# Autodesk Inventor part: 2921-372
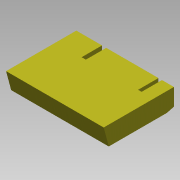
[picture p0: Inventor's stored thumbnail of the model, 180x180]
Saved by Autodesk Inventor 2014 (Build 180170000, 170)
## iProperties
Company: NHTSA/VRTC
Created: 2012-02
Part Number: 2921-372
Project: CHILD SIDE IMPACT SLED
Material: Polyurethane Foam
Description: SEAT BOTTOM CUSHION
Document SubType Name: Modeling
Designer: Dave Walker
Mass: 26828.4 g
Surface Area: 10956.6 cm^2
Volume: 42721.2 cm^3
Density: 0.627988 g/cm^3
Appearance: Canary
Title: Seat Bottom Cushion
Subject: Child Side Impact Sled
Author: Dave Walker
Comments: POLYURETHANE FOAM DENSITY ACCORDING TO ISO 485 (kg/m³)  BEARING STRENGTH ACCORDING TO ISO 2439B (N) p - 25% p - 40% BEARING STRENGTH FACTOR ACCORDEING TO ISO 3386 (kPa) ELONGATION AT RUPTURE ACCORDING
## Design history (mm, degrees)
sketch "Sketch2"
  geometry: L1 (-450, 135)-(50, 135); L2 (50, 135)-(50, 13.397); L3 (0, 0)-(-413.827, 0); L4 (-413.827, 0)-(-450, 135); L5 (0, 0)-(50, 13.397); 1 further point
  constraints: 10 end point, 1 coincident, 1 horizontal, 1 parallel, 1 vertical
  dimensions: "d9" = 15 deg angle of L3 L5; "d32" = 135 distance between parallel lines of L1 L3; "d34" = 500 horizontal distance of L2.end L1.start; "d35" = 50 horizontal distance of L2.end L3.start; "d37" = 75 deg angle of L1 L4
extrude "Extrusion2" new body sketch "Sketch2" stored distance "d13" = 695; taper "d14" = 0 deg
sketch "Sketch3"
  geometry: L1 (585, 0)-(610, 0); L2 (610, 0)-(610, -145); L3 (610, -145)-(585, -145); L4 (585, -145)-(585, 0); L5 (183, 0)-(213, 0); L6 (213, 0)-(213, -145); L7 (213, -145)-(183, -145); L8 (183, -145)-(183, 0); L9 (695, 0)-(0, 0) reference; L10 (695, 0)-(695, 0) reference; L11 (0, -500)-(695, -500) reference; L12 (695, -500)-(695, 0) reference; 1 further point
  constraints: 16 end point, 4 parallel, 3 collinear, 2 horizontal, 2 perpendicular
  dimensions: "d16" = 25 distance between parallel lines of L4 L2; "d17" = 397 distance between parallel lines of L6 L2; "d18" = 30 distance between parallel lines of L8 L6; "d36" = 145 distance between parallel lines of L3 L9; "d38" = 85 distance between parallel lines of L2 L12
extrude "Extrusion3" cut sketch "Sketch3" stored distance "d20" = 700; taper "d21" = 0 deg
workplane "Work Plane1"
workplane "Work Plane2"
body "Solid2"
other parameters: "d25" = 0, "d31" = 0
